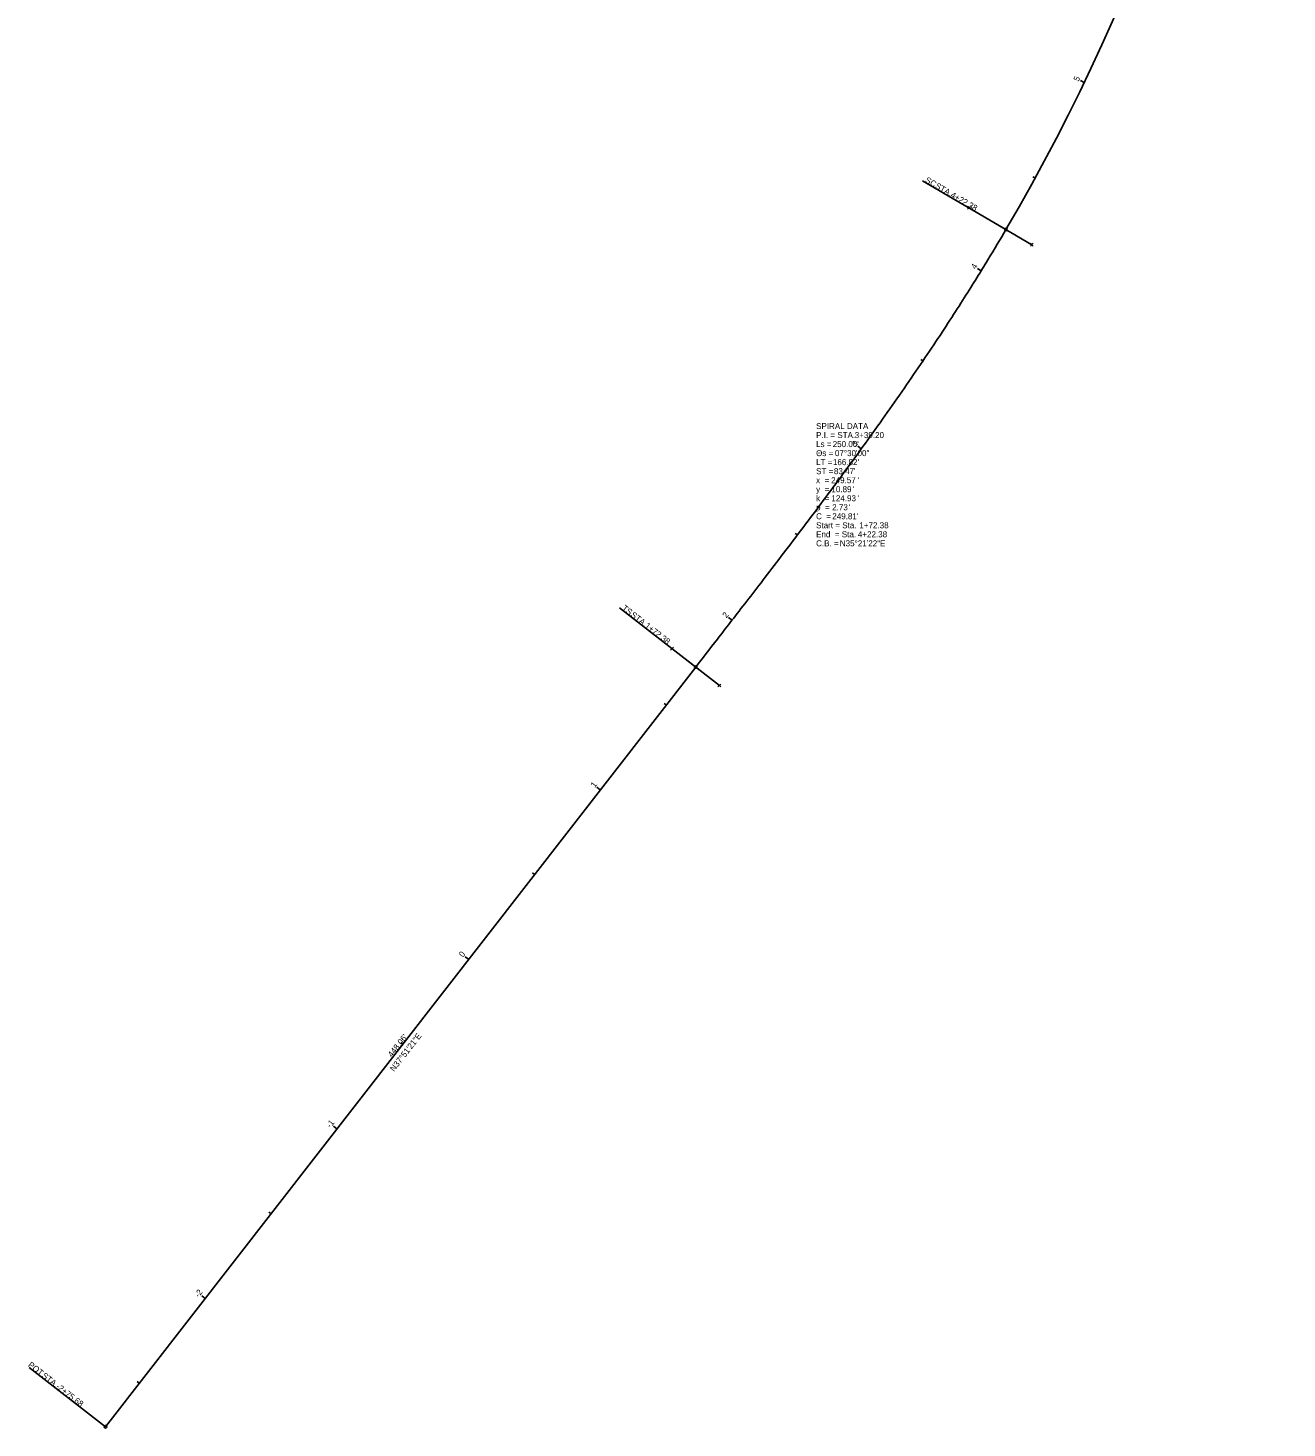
# Model space of a CAD drawing. Extents: x 1609531 to 1610891, y 471231 to 473177.
# Drawn here: x 1609531 to 1610117, y 471231 to 471883 of the extents above; entities that cross this region are included whole.
import ezdxf

# ---------------------------------------------------------------- set-up
doc = ezdxf.new("R2010")
doc.units = 0
for name, color, linetype in [('BR_X_SV_Shot_Marker', 7, 'Continuous'), ('Default', 7, 'Continuous'), ('PV_X_COP', 7, 'Continuous'), ('PV_X_EOP', 7, 'Continuous'), ('PV_X_Shoulder_Aggregate', 7, 'Continuous'), ('RD_X_Cells', 7, 'Continuous'), ('SV_X_Control_Cells_Found', 7, 'Continuous'), ('UT_X_Misc_Cells', 7, 'Continuous'), ('UT_X_Telecom_Cells', 7, 'Continuous')]:
    doc.layers.add(name, color=color, linetype=linetype)

msp = doc.modelspace()

# ---------------------------------------------------------------- linework, layer by layer
at = {"layer": 'Default'}
msp.add_line((1609566.8, 471231.37), (1609841.76, 471585.14), dxfattribs=at)
msp.add_arc((1609162.3, 472271.47), 954.93, 329.64417, 15.75667, dxfattribs=at)
msp.add_open_spline([(1609841.76, 471585.14), (1609844.96, 471589.25), (1609851.35, 471597.48), (1609864.12, 471613.94), (1609880.02, 471634.57), (1609898.89, 471659.47), (1609917.46, 471684.61), (1609935.61, 471710.05), (1609953.24, 471735.86), (1609967.4, 471757.71), (1609978.35, 471775.44), (1609983.69, 471784.38), (1609986.32, 471788.88)], degree=3, dxfattribs=at)
at = {"layer": 'PV_X_COP'}
for p, q in [((1609968.39, 471798.32), (1609969.73, 471799.65)), ((1609968.39, 471799.65), (1609969.73, 471798.32)), ((1609997.73, 471781.14), (1609999.06, 471782.47)), ((1609997.73, 471782.47), (1609999.06, 471781.14)), ((1609830.04, 471593.07), (1609831.38, 471594.4)), ((1609830.04, 471594.4), (1609831.38, 471593.07)), ((1609852.15, 471575.88), (1609853.48, 471577.22)), ((1609852.15, 471577.22), (1609853.48, 471575.88))]:
    msp.add_line(p, q, dxfattribs=at)
at = {"layer": 'PV_X_Shoulder_Aggregate'}
for p, q in [((1610022.78, 471857.38), (1610020.98, 471858.24)), ((1609999.93, 471812.91), (1609998.88, 471813.49)), ((1609974.79, 471769.7), (1609973.09, 471770.75)), ((1609947.63, 471727.72), (1609946.63, 471728.39)), ((1609918.93, 471686.78), (1609917.31, 471687.96)), ((1609889.14, 471646.63), (1609888.18, 471647.35)), ((1609858.7, 471606.96), (1609857.12, 471608.18)), ((1609828.03, 471567.47), (1609827.08, 471568.21)), ((1609797.34, 471527.99), (1609795.76, 471529.22)), ((1609766.66, 471488.51), (1609765.71, 471489.25)), ((1609735.98, 471449.04), (1609734.4, 471450.26)), ((1609705.29, 471409.56), (1609704.34, 471410.29)), ((1609674.61, 471370.08), (1609673.03, 471371.31)), ((1609643.92, 471330.6), (1609642.98, 471331.34)), ((1609613.24, 471291.12), (1609611.66, 471292.35)), ((1609582.56, 471251.65), (1609581.61, 471252.38))]:
    msp.add_line(p, q, dxfattribs=at)
at = {"layer": 'RD_X_Cells'}
for p, q in [((1609969.06, 471798.99), (1609998.4, 471781.8)), ((1609830.71, 471593.73), (1609852.82, 471576.55))]:
    msp.add_line(p, q, dxfattribs=at)
at = {"layer": 'SV_X_Control_Cells_Found'}
for p, q in [((1609986.32, 471788.88), (1609947.49, 471811.62)), ((1609841.76, 471585.14), (1609806.23, 471612.76)), ((1609566.8, 471231.37), (1609531.27, 471258.99))]:
    msp.add_line(p, q, dxfattribs=at)
for centre in [(1609986.32, 471788.88), (1609841.76, 471585.14), (1609566.8, 471231.37)]:
    msp.add_circle(centre, 0.6, dxfattribs=at)
at = {"layer": 'UT_X_Misc_Cells'}
msp.add_line((1609566.8, 471231.37), (1609841.76, 471585.14), dxfattribs=at)
msp.add_arc((1609162.3, 472271.47), 954.93, 329.64417, 15.75667, dxfattribs=at)
msp.add_open_spline([(1609841.76, 471585.14), (1609844.96, 471589.25), (1609851.35, 471597.48), (1609864.12, 471613.94), (1609880.02, 471634.57), (1609898.89, 471659.47), (1609917.46, 471684.61), (1609935.61, 471710.05), (1609953.24, 471735.86), (1609967.4, 471757.71), (1609978.35, 471775.44), (1609983.69, 471784.38), (1609986.32, 471788.88)], degree=3, dxfattribs=at)

# ---------------------------------------------------------------- texts
at = {"layer": 'BR_X_SV_Shot_Marker'}
for s, p in [('SPIRAL DATA', (1609897.86, 471695.96)), ('P.I. = STA. ', (1609897.86, 471691.76)), ('Ls = ', (1609897.86, 471687.56)), ("250.00'", (1609905.6, 471687.56)), ('3+39.20', (1609915.85, 471691.76)), ('Θs = ', (1609897.86, 471683.36)), ('07°30\'00"', (1609906.64, 471683.36)), ('ST = ', (1609897.86, 471674.96)), ('LT = ', (1609897.86, 471679.16)), ("166.82'", (1609905.7, 471679.16)), ("83.47'", (1609906.16, 471674.96)), ('x  = ', (1609897.86, 471670.76)), ('249.57', (1609904.89, 471670.76)), ('10.89', (1609904.99, 471666.56)), ("'", (1609915.01, 471666.56)), ("'", (1609917.14, 471670.76)), ('y  = ', (1609897.86, 471666.56)), ('k  = ', (1609897.86, 471662.36)), ('124.93', (1609904.99, 471662.36)), ("'", (1609917.24, 471662.36)), ('C  = ', (1609897.86, 471653.96)), ('p  = ', (1609897.86, 471658.16)), ('2.73', (1609905.34, 471658.16)), ("249.81'", (1609905.4, 471653.96)), ("'", (1609913.12, 471658.16)), ('Start = Sta. ', (1609897.86, 471649.76)), ('1+72.38', (1609918.01, 471649.76)), ('C.B. = ', (1609897.86, 471641.36)), ('End  = Sta. ', (1609897.86, 471645.56)), ('N35°21\'22"E', (1609908.92, 471641.36)), ('4+22.38', (1609917.32, 471645.56))]:
    msp.add_text(s, height=2.8, dxfattribs=at).set_placement(p)
at = {"layer": 'PV_X_EOP'}
msp.add_text("448.06'", height=2.8, rotation=52.14417, dxfattribs=at).set_placement((1609700.3, 471403.2))
at = {"layer": 'PV_X_Shoulder_Aggregate'}
for s, rotation, p in [('5', 64.30136, (1610020.11, 471857.58)), ('4', 58.36147, (1609972.11, 471770.12)), ('3', 54.09859, (1609916.34, 471687.47)), ('2', 52.23571, (1609856.13, 471607.72)), ('1', 52.14417, (1609794.76, 471528.75)), ('0', 52.14417, (1609733.37, 471449.75)), ('-1', 52.14417, (1609671.61, 471370.3)), ('-2', 52.14417, (1609610.25, 471291.35))]:
    msp.add_text(s, height=2.8, rotation=rotation, dxfattribs=at).set_placement(p)
at = {"layer": 'SV_X_Control_Cells_Found'}
for s, rotation, p in [('SC', 329.64417, (1609948.4, 471811.13)), (' STA. ', 329.64417, (1609952.16, 471808.93)), ('4+22.38', 329.64417, (1609960.21, 471804.21)), ('TS', 322.14417, (1609807.17, 471612.07)), (' STA. ', 322.14417, (1609810.42, 471609.55)), ('1+72.38', 322.14417, (1609817.78, 471603.83)), ('POT', 322.14417, (1609530.48, 471259.64)), (' STA. ', 322.14417, (1609536.11, 471255.27)), ('-2+75.68', 322.14417, (1609543.47, 471249.55))]:
    msp.add_text(s, height=2.8, rotation=rotation, dxfattribs=at).set_placement(p)
at = {"layer": 'UT_X_Telecom_Cells'}
msp.add_text('N37°51\'21"E', height=2.8, rotation=52.14417, dxfattribs=at).set_placement((1609701.25, 471396.53))

doc.saveas('drawing.dxf')
